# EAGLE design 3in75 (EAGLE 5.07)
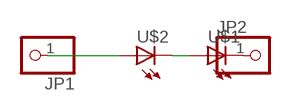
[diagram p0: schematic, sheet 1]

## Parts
JP1  PINHD-1X11X0.4  [1X01]
JP2  PINHD-1X11X0.4  [1X01]
U$1  LEDSMT1206  [1206]
U$2  LEDSMT1206  [1206]

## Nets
N$1: JP1.1 U$2.A
N$3: U$1.A U$2.C
N$4: JP2.1 U$1.C

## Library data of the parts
JP1 JP2 = pinhead:PINHD-1X1: PIN HEADER
U$1 U$2 = led(2):LED: LED

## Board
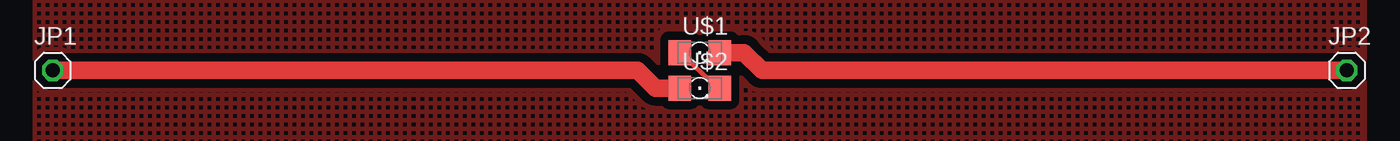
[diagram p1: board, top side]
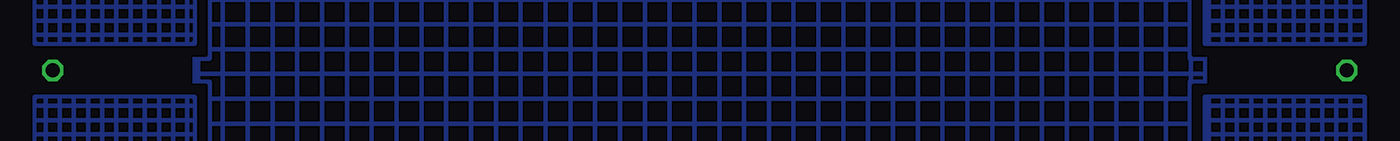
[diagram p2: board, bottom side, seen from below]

No outline drawn. Coordinates in mm, seen from the top.
Copper layers (1*16): Top 0.035mm / dielectric 1.5mm / Bottom 0.035mm
Design rules "default": minimum track width 10mil, minimum drill 24mil, track to track 8mil, track to pad 8mil, pad to pad 8mil, via to via 8mil, smd to smd 8mil, copper to edge 40mil, drill to drill 8mil, minimum pad ring 10mil, minimum via ring 8mil, stop-mask expansion 4mil, vias tented up to drill 0mil, thermal gap 10mil

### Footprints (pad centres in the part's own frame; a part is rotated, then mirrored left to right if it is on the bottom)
1X01 = drill 1.016 octagon: 1 0,0
1206 = smd 1.6 x 1.803: A -1.422,0; C 1.422,0

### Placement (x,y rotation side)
JP1  1.27,12.7 0 top
JP2  93.98,12.7 0 top
U$1  47.62,13.97 0 top
U$2  47.62,11.43 0 top

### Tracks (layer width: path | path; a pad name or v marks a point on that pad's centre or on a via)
N$1
  Top 1.27: JP1.1 43.18,12.7 44.45,11.43 U$2.A
N$2
  pour Top (isolate 0.61, hatched): 0,25.4 95.25,25.4 95.25,0 0,0
  pour Bottom (isolate 0.813, rank 2, hatched): 11.43,25.4 83.82,25.4 83.82,0 11.43,0
N$3
  Top 0.305: U$2.C 48.26,12.06 U$1.A
N$4
  Top 1.27: JP2.1 52.07,12.7 50.8,13.97 U$1.C
N$5
  pour Bottom (hatched): 0,25.4 11.43,25.4 11.43,14.61 0,14.61
  pour Bottom (hatched): 0,10.79 11.43,10.79 11.43,0 0,0
  pour Bottom (hatched): 83.82,10.79 95.25,10.79 95.25,0 83.82,0
  pour Bottom (hatched): 83.82,25.4 95.25,25.4 95.25,14.61 83.82,14.61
